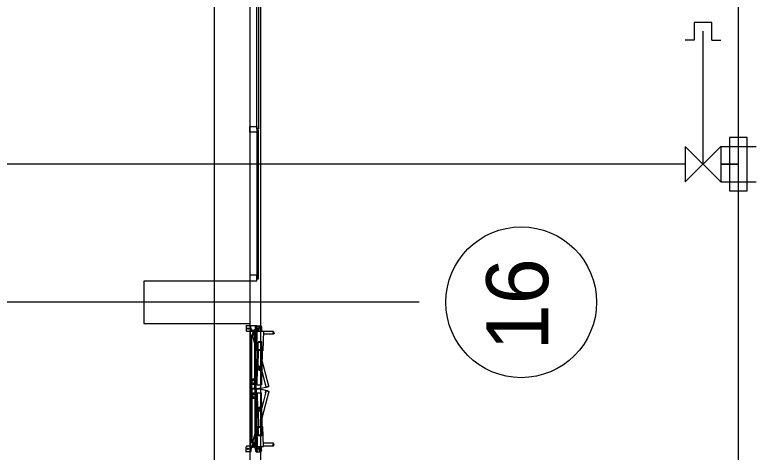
# Model space of a CAD drawing. Extents: x -264205 to -263659, y -1242401 to -1241986.
# Drawn here: x -263798.36 to -263787.89, y -1242184 to -1242177.83 of the extents above; entities that cross this region are included whole.
import ezdxf

# ---------------------------------------------------------------- set-up
doc = ezdxf.new("R2010")
doc.units = 0
for name, color, linetype in [('HESCON_OSI_STAVBY_KFA', 7, 'Continuous'), ('PROJEKT_OBRUBNIKY_KOMUNIKACIE', 7, 'Continuous'), ('SITUACIA_DSP_2D', 7, 'Continuous')]:
    doc.layers.add(name, color=color, linetype=linetype)

msp = doc.modelspace()

# ---------------------------------------------------------------- linework, layer by layer
at = {"layer": 'HESCON_OSI_STAVBY_KFA'}
for p, q in [((-263795.543, -1242083.237), (-263795.543, -1242246.707)), ((-263792.653, -1242181.882), (-263857.913, -1242181.882)), ((-263792.653, -1242181.882), (-263792.653, -1242181.882))]:
    msp.add_line(p, q, dxfattribs=at)
msp.add_circle((-263791.21, -1242181.882), 1.064, dxfattribs=at)
at = {"layer": 'PROJEKT_OBRUBNIKY_KOMUNIKACIE'}
msp.add_lwpolyline([(-263794.893, -1242227.382), (-263808.968, -1242241.457), (-263894.968, -1242241.457), (-263909.043, -1242227.382), (-263909.043, -1242196.333), (-263914.143, -1242196.333), (-263914.143, -1242132.433), (-263909.043, -1242132.433), (-263909.043, -1242101.382), (-263894.968, -1242087.307), (-263808.968, -1242087.307), (-263794.893, -1242101.382), (-263794.893, -1242227.382)], dxfattribs=at)
at = {"layer": 'SITUACIA_DSP_2D'}
for p, q in [((-263788.143, -1242250.14), (-263788.143, -1242082.64)), ((-263794.893, -1242101.382), (-263794.893, -1242227.382)), ((-263795.043, -1242101.769), (-263795.043, -1242226.995)), ((-263794.943, -1242179.432), (-263794.943, -1242177.332)), ((-263794.918, -1242177.332), (-263794.918, -1242179.432)), ((-263788.768, -1242177.932), (-263788.768, -1242178.182)), ((-263788.518, -1242177.932), (-263788.768, -1242177.932)), ((-263788.518, -1242178.182), (-263788.518, -1242177.932)), ((-263788.643, -1242179.932), (-263788.643, -1242178.057)), ((-263788.768, -1242178.182), (-263788.893, -1242178.182)), ((-263788.518, -1242178.182), (-263788.393, -1242178.182)), ((-263795.043, -1242179.482), (-263795.043, -1242179.402)), ((-263795.043, -1242179.402), (-263794.943, -1242179.402)), ((-263794.943, -1242179.402), (-263794.943, -1242179.492)), ((-263794.918, -1242179.432), (-263794.943, -1242179.432)), ((-263794.918, -1242179.452), (-263794.943, -1242179.452)), ((-263794.943, -1242179.452), (-263794.943, -1242181.552)), ((-263794.918, -1242181.552), (-263794.918, -1242179.452)), ((-263794.943, -1242179.482), (-263795.043, -1242179.482)), ((-263794.943, -1242179.492), (-263794.943, -1242179.482)), ((-263788.268, -1242179.557), (-263788.268, -1242180.307)), ((-263788.018, -1242179.557), (-263788.268, -1242179.557)), ((-263788.018, -1242180.307), (-263788.018, -1242179.557)), ((-263788.893, -1242179.682), (-263788.893, -1242180.182)), ((-263788.393, -1242180.182), (-263788.893, -1242179.682)), ((-263788.893, -1242180.182), (-263788.393, -1242179.682)), ((-263788.393, -1242179.682), (-263788.393, -1242180.182)), ((-263788.393, -1242179.682), (-263787.893, -1242179.682)), ((-263788.893, -1242179.932), (-263800.593, -1242179.932)), ((-263788.143, -1242179.932), (-263788.393, -1242179.932)), ((-263788.393, -1242179.932), (-263788.143, -1242179.932)), ((-263788.393, -1242180.182), (-263787.893, -1242180.182)), ((-263788.268, -1242180.307), (-263788.018, -1242180.307)), ((-263794.943, -1242181.497), (-263795.043, -1242181.497)), ((-263795.043, -1242181.497), (-263795.043, -1242181.577)), ((-263794.943, -1242181.537), (-263794.943, -1242181.497)), ((-263794.943, -1242181.577), (-263794.943, -1242181.537)), ((-263795.038, -1242181.582), (-263796.538, -1242181.582)), ((-263796.538, -1242181.582), (-263796.538, -1242182.182)), ((-263795.043, -1242181.577), (-263794.943, -1242181.577)), ((-263795.038, -1242182.182), (-263795.038, -1242181.582)), ((-263794.943, -1242181.552), (-263794.918, -1242181.552)), ((-263796.538, -1242182.182), (-263795.038, -1242182.182)), ((-263795.093, -1242182.208), (-263795.093, -1242182.284)), ((-263795.033, -1242182.214), (-263795.093, -1242182.214)), ((-263795.055, -1242182.254), (-263795.081, -1242182.254)), ((-263795.068, -1242182.241), (-263795.068, -1242182.267)), ((-263795.043, -1242182.208), (-263794.943, -1242182.208)), ((-263795.033, -1242183.102), (-263795.033, -1242182.208)), ((-263795.025, -1242182.224), (-263795.033, -1242182.224)), ((-263795.025, -1242182.245), (-263795.025, -1242182.224)), ((-263794.96, -1242182.245), (-263794.96, -1242182.224)), ((-263794.953, -1242182.224), (-263794.96, -1242182.224)), ((-263794.953, -1242183.102), (-263794.953, -1242182.208)), ((-263794.953, -1242182.213), (-263794.943, -1242182.213)), ((-263794.953, -1242182.213), (-263794.953, -1242182.283)), ((-263794.933, -1242182.223), (-263794.947, -1242182.223)), ((-263794.933, -1242182.272), (-263794.947, -1242182.272)), ((-263794.943, -1242182.213), (-263794.893, -1242182.213)), ((-263794.943, -1242182.213), (-263794.943, -1242182.283)), ((-263794.943, -1242182.232), (-263794.943, -1242182.215)), ((-263794.941, -1242182.215), (-263794.943, -1242182.215)), ((-263794.941, -1242182.232), (-263794.943, -1242182.232)), ((-263794.943, -1242182.253), (-263794.908, -1242182.253)), ((-263794.943, -1242182.281), (-263794.943, -1242182.264)), ((-263794.941, -1242182.264), (-263794.943, -1242182.264)), ((-263794.941, -1242182.232), (-263794.941, -1242182.215)), ((-263794.941, -1242182.23), (-263794.941, -1242182.217)), ((-263794.941, -1242182.217), (-263794.935, -1242182.217)), ((-263794.941, -1242182.223), (-263794.936, -1242182.223)), ((-263794.935, -1242182.23), (-263794.941, -1242182.23)), ((-263794.941, -1242182.281), (-263794.941, -1242182.264)), ((-263794.941, -1242182.279), (-263794.941, -1242182.266)), ((-263794.941, -1242182.266), (-263794.935, -1242182.266)), ((-263794.941, -1242182.272), (-263794.936, -1242182.272)), ((-263794.935, -1242182.217), (-263794.935, -1242182.23)), ((-263794.935, -1242182.266), (-263794.935, -1242182.279)), ((-263794.908, -1242182.254), (-263794.927, -1242182.254)), ((-263794.918, -1242182.253), (-263794.918, -1242182.264)), ((-263794.909, -1242182.289), (-263794.908, -1242182.233)), ((-263794.877, -1242182.233), (-263794.908, -1242182.233)), ((-263794.899, -1242182.223), (-263794.905, -1242182.233)), ((-263794.905, -1242182.233), (-263794.899, -1242182.244)), ((-263794.887, -1242182.223), (-263794.899, -1242182.223)), ((-263794.899, -1242182.244), (-263794.887, -1242182.244)), ((-263794.893, -1242182.218), (-263794.893, -1242182.249)), ((-263794.881, -1242182.233), (-263794.887, -1242182.223)), ((-263794.887, -1242182.244), (-263794.881, -1242182.233)), ((-263794.878, -1242182.234), (-263794.879, -1242182.29)), ((-263795.033, -1242182.294), (-263795.083, -1242182.294)), ((-263794.953, -1242182.288), (-263795.033, -1242182.288)), ((-263794.953, -1242182.294), (-263795.033, -1242182.294)), ((-263795.013, -1242183.097), (-263795.013, -1242182.339)), ((-263794.973, -1242182.339), (-263795.013, -1242182.339)), ((-263795.005, -1242182.288), (-263794.98, -1242182.288)), ((-263795.005, -1242182.288), (-263795.005, -1242182.298)), ((-263795.005, -1242182.298), (-263794.98, -1242182.298)), ((-263795.005, -1242182.339), (-263795.005, -1242182.329)), ((-263795.005, -1242182.329), (-263794.98, -1242182.329)), ((-263795.005, -1242182.343), (-263794.967, -1242182.333)), ((-263795.005, -1242182.339), (-263794.98, -1242182.339)), ((-263794.953, -1242182.54), (-263795.005, -1242182.343)), ((-263794.994, -1242182.298), (-263795.001, -1242182.308)), ((-263795.001, -1242182.319), (-263794.994, -1242182.329)), ((-263794.977, -1242182.325), (-263795.001, -1242182.332)), ((-263794.998, -1242182.341), (-263795.001, -1242182.332)), ((-263794.99, -1242182.329), (-263794.999, -1242182.321)), ((-263794.992, -1242182.298), (-263794.994, -1242182.298)), ((-263794.994, -1242182.329), (-263794.992, -1242182.329)), ((-263794.985, -1242182.308), (-263794.992, -1242182.298)), ((-263794.992, -1242182.329), (-263794.985, -1242182.319)), ((-263794.988, -1242182.328), (-263794.99, -1242182.329)), ((-263794.983, -1242182.317), (-263794.988, -1242182.328)), ((-263794.987, -1242182.305), (-263794.977, -1242182.312)), ((-263794.977, -1242182.314), (-263794.987, -1242182.322)), ((-263794.98, -1242182.288), (-263794.98, -1242182.298)), ((-263794.98, -1242182.339), (-263794.98, -1242182.329)), ((-263794.977, -1242182.301), (-263794.977, -1242182.326)), ((-263794.967, -1242182.301), (-263794.977, -1242182.301)), ((-263794.977, -1242182.312), (-263794.977, -1242182.314)), ((-263794.974, -1242182.335), (-263794.977, -1242182.325)), ((-263794.967, -1242182.326), (-263794.977, -1242182.326)), ((-263794.973, -1242183.097), (-263794.973, -1242182.339)), ((-263794.967, -1242182.333), (-263794.967, -1242182.293)), ((-263794.937, -1242182.293), (-263794.967, -1242182.293)), ((-263794.967, -1242182.301), (-263794.967, -1242182.326)), ((-263794.938, -1242182.333), (-263794.967, -1242182.333)), ((-263794.953, -1242182.386), (-263794.967, -1242182.333)), ((-263794.953, -1242182.283), (-263794.943, -1242182.283)), ((-263794.937, -1242182.294), (-263794.953, -1242182.294)), ((-263794.941, -1242182.281), (-263794.943, -1242182.281)), ((-263794.943, -1242182.564), (-263794.937, -1242182.289)), ((-263794.935, -1242182.279), (-263794.941, -1242182.279)), ((-263794.937, -1242182.289), (-263794.85, -1242182.29)), ((-263794.85, -1242182.29), (-263794.856, -1242182.565)), ((-263794.707, -1242182.333), (-263794.851, -1242182.333)), ((-263794.707, -1242182.293), (-263794.85, -1242182.293)), ((-263794.707, -1242182.305), (-263794.722, -1242182.309)), ((-263794.722, -1242182.309), (-263794.692, -1242182.318)), ((-263794.707, -1242182.293), (-263794.707, -1242182.305)), ((-263794.692, -1242182.318), (-263794.707, -1242182.322)), ((-263794.707, -1242182.322), (-263794.707, -1242182.333)), ((-263794.924, -1242182.564), (-263794.922, -1242182.438)), ((-263794.872, -1242182.439), (-263794.922, -1242182.438)), ((-263794.872, -1242182.449), (-263794.922, -1242182.448)), ((-263794.874, -1242182.565), (-263794.872, -1242182.439)), ((-263794.856, -1242182.565), (-263794.943, -1242182.564)), ((-263794.939, -1242183.045), (-263794.93, -1242182.564)), ((-263794.874, -1242182.555), (-263794.924, -1242182.554)), ((-263794.924, -1242182.787), (-263794.919, -1242182.564)), ((-263794.884, -1242182.788), (-263794.879, -1242182.565)), ((-263794.869, -1242182.565), (-263794.878, -1242183.046)), ((-263794.772, -1242183.066), (-263794.871, -1242182.689)), ((-263794.884, -1242182.788), (-263794.924, -1242182.787)), ((-263794.914, -1242182.792), (-263794.914, -1242182.787)), ((-263794.894, -1242182.792), (-263794.914, -1242182.792)), ((-263794.912, -1242182.792), (-263794.914, -1242182.793)), ((-263794.914, -1242182.799), (-263794.914, -1242182.793)), ((-263794.913, -1242182.8), (-263794.914, -1242182.799)), ((-263794.896, -1242182.8), (-263794.913, -1242182.8)), ((-263794.895, -1242182.792), (-263794.912, -1242182.792)), ((-263794.909, -1242182.799), (-263794.909, -1242182.793)), ((-263794.909, -1242182.808), (-263794.909, -1242182.8)), ((-263794.899, -1242182.8), (-263794.899, -1242182.793)), ((-263794.899, -1242182.808), (-263794.899, -1242182.8)), ((-263794.896, -1242182.8), (-263794.894, -1242182.8)), ((-263794.895, -1242182.792), (-263794.894, -1242182.793)), ((-263794.894, -1242182.792), (-263794.894, -1242182.787)), ((-263794.894, -1242182.8), (-263794.894, -1242182.793)), ((-263794.909, -1242182.808), (-263794.917, -1242182.821)), ((-263794.909, -1242182.808), (-263794.899, -1242182.808)), ((-263794.899, -1242182.808), (-263794.892, -1242182.822)), ((-263794.811, -1242183.076), (-263794.874, -1242182.833)), ((-263795.007, -1242183.04), (-263795.007, -1242182.965)), ((-263794.953, -1242182.965), (-263795.007, -1242182.965)), ((-263795, -1242182.976), (-263794.993, -1242182.972)), ((-263795, -1242182.984), (-263795, -1242182.976)), ((-263794.993, -1242182.988), (-263795, -1242182.984)), ((-263794.993, -1242182.972), (-263794.986, -1242182.976)), ((-263794.986, -1242182.984), (-263794.993, -1242182.988)), ((-263794.986, -1242182.976), (-263794.986, -1242182.984)), ((-263794.947, -1242182.965), (-263794.953, -1242182.965)), ((-263794.947, -1242183.04), (-263794.947, -1242182.965)), ((-263795.033, -1242183.102), (-263795.033, -1242183.997)), ((-263795.015, -1242183.095), (-263795.015, -1242183.065)), ((-263795.013, -1242183.065), (-263795.015, -1242183.065)), ((-263795.015, -1242183.109), (-263795.015, -1242183.139)), ((-263794.973, -1242183.097), (-263795.013, -1242183.097)), ((-263795.013, -1242183.107), (-263795.013, -1242183.866)), ((-263794.973, -1242183.107), (-263795.013, -1242183.107)), ((-263794.975, -1242183.099), (-263795.011, -1242183.099)), ((-263794.975, -1242183.105), (-263795.011, -1242183.105)), ((-263794.953, -1242183.04), (-263795.007, -1242183.04)), ((-263795, -1242183.021), (-263794.993, -1242183.017)), ((-263795, -1242183.029), (-263795, -1242183.021)), ((-263794.993, -1242183.033), (-263795, -1242183.029)), ((-263794.993, -1242183.017), (-263794.986, -1242183.021)), ((-263794.986, -1242183.029), (-263794.993, -1242183.033)), ((-263794.986, -1242183.021), (-263794.986, -1242183.029)), ((-263794.976, -1242183.096), (-263794.967, -1242183.096)), ((-263794.976, -1242183.109), (-263794.967, -1242183.109)), ((-263794.971, -1242183.065), (-263794.973, -1242183.065)), ((-263794.97, -1242183.08), (-263794.973, -1242183.08)), ((-263794.973, -1242183.107), (-263794.973, -1242183.866)), ((-263794.971, -1242183.095), (-263794.971, -1242183.065)), ((-263794.971, -1242183.109), (-263794.971, -1242183.139)), ((-263794.947, -1242183.04), (-263794.953, -1242183.04)), ((-263794.953, -1242183.102), (-263794.953, -1242183.997)), ((-263794.939, -1242183.045), (-263794.878, -1242183.046)), ((-263794.819, -1242183.045), (-263794.821, -1242183.046)), ((-263794.821, -1242183.046), (-263794.814, -1242183.075)), ((-263794.811, -1242183.076), (-263794.772, -1242183.066)), ((-263794.809, -1242183.078), (-263794.774, -1242183.068)), ((-263794.779, -1242183.035), (-263794.781, -1242183.035)), ((-263794.771, -1242183.064), (-263794.779, -1242183.035)), ((-263795.013, -1242183.139), (-263795.015, -1242183.139)), ((-263795.007, -1242183.165), (-263795.007, -1242183.24)), ((-263794.953, -1242183.165), (-263795.007, -1242183.165)), ((-263794.993, -1242183.172), (-263795, -1242183.176)), ((-263795, -1242183.176), (-263795, -1242183.184)), ((-263795, -1242183.184), (-263794.993, -1242183.188)), ((-263794.993, -1242183.217), (-263795, -1242183.221)), ((-263794.986, -1242183.176), (-263794.993, -1242183.172)), ((-263794.993, -1242183.188), (-263794.986, -1242183.184)), ((-263794.986, -1242183.221), (-263794.993, -1242183.217)), ((-263794.986, -1242183.184), (-263794.986, -1242183.176)), ((-263794.97, -1242183.125), (-263794.973, -1242183.125)), ((-263794.971, -1242183.139), (-263794.973, -1242183.139)), ((-263794.947, -1242183.165), (-263794.953, -1242183.165)), ((-263794.947, -1242183.165), (-263794.947, -1242183.24)), ((-263794.939, -1242183.16), (-263794.878, -1242183.159)), ((-263794.939, -1242183.16), (-263794.93, -1242183.641)), ((-263794.869, -1242183.64), (-263794.878, -1242183.159)), ((-263794.811, -1242183.129), (-263794.874, -1242183.372)), ((-263794.772, -1242183.139), (-263794.871, -1242183.516)), ((-263794.821, -1242183.159), (-263794.814, -1242183.13)), ((-263794.819, -1242183.16), (-263794.821, -1242183.159)), ((-263794.811, -1242183.129), (-263794.772, -1242183.139)), ((-263794.809, -1242183.127), (-263794.774, -1242183.137)), ((-263794.779, -1242183.17), (-263794.781, -1242183.17)), ((-263794.771, -1242183.141), (-263794.779, -1242183.17)), ((-263794.953, -1242183.24), (-263795.007, -1242183.24)), ((-263795, -1242183.221), (-263795, -1242183.229)), ((-263795, -1242183.229), (-263794.993, -1242183.233)), ((-263794.993, -1242183.233), (-263794.986, -1242183.229)), ((-263794.986, -1242183.229), (-263794.986, -1242183.221)), ((-263794.947, -1242183.24), (-263794.953, -1242183.24)), ((-263794.884, -1242183.417), (-263794.924, -1242183.418)), ((-263794.924, -1242183.418), (-263794.919, -1242183.641)), ((-263794.909, -1242183.397), (-263794.917, -1242183.384)), ((-263794.913, -1242183.405), (-263794.914, -1242183.406)), ((-263794.914, -1242183.406), (-263794.914, -1242183.412)), ((-263794.912, -1242183.413), (-263794.914, -1242183.412)), ((-263794.914, -1242183.413), (-263794.914, -1242183.418)), ((-263794.894, -1242183.413), (-263794.914, -1242183.413)), ((-263794.896, -1242183.405), (-263794.913, -1242183.405)), ((-263794.895, -1242183.413), (-263794.912, -1242183.413)), ((-263794.909, -1242183.397), (-263794.899, -1242183.397)), ((-263794.909, -1242183.397), (-263794.909, -1242183.405)), ((-263794.909, -1242183.406), (-263794.909, -1242183.412)), ((-263794.899, -1242183.397), (-263794.892, -1242183.383)), ((-263794.899, -1242183.397), (-263794.899, -1242183.405)), ((-263794.899, -1242183.405), (-263794.899, -1242183.412)), ((-263794.896, -1242183.405), (-263794.894, -1242183.405)), ((-263794.895, -1242183.413), (-263794.894, -1242183.412)), ((-263794.894, -1242183.405), (-263794.894, -1242183.412)), ((-263794.894, -1242183.413), (-263794.894, -1242183.418)), ((-263794.884, -1242183.417), (-263794.879, -1242183.64)), ((-263794.953, -1242183.665), (-263795.005, -1242183.862)), ((-263794.856, -1242183.64), (-263794.943, -1242183.641)), ((-263794.943, -1242183.641), (-263794.937, -1242183.916)), ((-263794.924, -1242183.641), (-263794.922, -1242183.767)), ((-263794.874, -1242183.65), (-263794.924, -1242183.651)), ((-263794.874, -1242183.64), (-263794.872, -1242183.766)), ((-263794.85, -1242183.915), (-263794.856, -1242183.64)), ((-263794.953, -1242183.819), (-263794.967, -1242183.872)), ((-263794.872, -1242183.756), (-263794.922, -1242183.757)), ((-263794.872, -1242183.766), (-263794.922, -1242183.767)), ((-263795.093, -1242183.997), (-263795.093, -1242183.921)), ((-263795.033, -1242183.911), (-263795.083, -1242183.911)), ((-263795.055, -1242183.951), (-263795.081, -1242183.951)), ((-263795.068, -1242183.964), (-263795.068, -1242183.938)), ((-263794.953, -1242183.911), (-263795.033, -1242183.911)), ((-263794.953, -1242183.917), (-263795.033, -1242183.917)), ((-263794.973, -1242183.866), (-263795.013, -1242183.866)), ((-263795.005, -1242183.862), (-263794.967, -1242183.872)), ((-263795.005, -1242183.866), (-263795.005, -1242183.876)), ((-263795.005, -1242183.866), (-263794.98, -1242183.866)), ((-263795.005, -1242183.876), (-263794.98, -1242183.876)), ((-263795.005, -1242183.907), (-263794.98, -1242183.907)), ((-263795.005, -1242183.917), (-263795.005, -1242183.907)), ((-263795.005, -1242183.917), (-263794.98, -1242183.917)), ((-263794.998, -1242183.864), (-263795.001, -1242183.873)), ((-263794.977, -1242183.88), (-263795.001, -1242183.873)), ((-263795.001, -1242183.886), (-263794.994, -1242183.876)), ((-263794.994, -1242183.907), (-263795.001, -1242183.897)), ((-263794.99, -1242183.876), (-263794.999, -1242183.884)), ((-263794.994, -1242183.876), (-263794.992, -1242183.876)), ((-263794.992, -1242183.907), (-263794.994, -1242183.907)), ((-263794.992, -1242183.876), (-263794.985, -1242183.886)), ((-263794.985, -1242183.897), (-263794.992, -1242183.907)), ((-263794.988, -1242183.877), (-263794.99, -1242183.876)), ((-263794.983, -1242183.888), (-263794.988, -1242183.877)), ((-263794.977, -1242183.89), (-263794.987, -1242183.883)), ((-263794.987, -1242183.9), (-263794.977, -1242183.892)), ((-263794.98, -1242183.866), (-263794.98, -1242183.876)), ((-263794.98, -1242183.917), (-263794.98, -1242183.907)), ((-263794.974, -1242183.87), (-263794.977, -1242183.88)), ((-263794.977, -1242183.904), (-263794.977, -1242183.879)), ((-263794.967, -1242183.879), (-263794.977, -1242183.879)), ((-263794.977, -1242183.892), (-263794.977, -1242183.89)), ((-263794.967, -1242183.904), (-263794.977, -1242183.904)), ((-263794.967, -1242183.871), (-263794.967, -1242183.911)), ((-263794.938, -1242183.871), (-263794.967, -1242183.871)), ((-263794.967, -1242183.904), (-263794.967, -1242183.879)), ((-263794.937, -1242183.911), (-263794.967, -1242183.911)), ((-263794.937, -1242183.911), (-263794.953, -1242183.911)), ((-263794.953, -1242183.922), (-263794.943, -1242183.922)), ((-263794.953, -1242183.992), (-263794.953, -1242183.922)), ((-263794.933, -1242183.932), (-263794.947, -1242183.932)), ((-263794.943, -1242183.992), (-263794.943, -1242183.922)), ((-263794.943, -1242183.924), (-263794.943, -1242183.941)), ((-263794.941, -1242183.924), (-263794.943, -1242183.924)), ((-263794.941, -1242183.941), (-263794.943, -1242183.941)), ((-263794.943, -1242183.951), (-263794.908, -1242183.951)), ((-263794.941, -1242183.924), (-263794.941, -1242183.941)), ((-263794.941, -1242183.926), (-263794.941, -1242183.939)), ((-263794.935, -1242183.926), (-263794.941, -1242183.926)), ((-263794.941, -1242183.932), (-263794.936, -1242183.932)), ((-263794.941, -1242183.939), (-263794.935, -1242183.939)), ((-263794.937, -1242183.916), (-263794.85, -1242183.915)), ((-263794.935, -1242183.939), (-263794.935, -1242183.926)), ((-263794.908, -1242183.951), (-263794.927, -1242183.951)), ((-263794.918, -1242183.951), (-263794.918, -1242183.941)), ((-263794.909, -1242183.916), (-263794.908, -1242183.972)), ((-263794.878, -1242183.971), (-263794.879, -1242183.915)), ((-263794.707, -1242183.871), (-263794.851, -1242183.871)), ((-263794.707, -1242183.911), (-263794.85, -1242183.911)), ((-263794.722, -1242183.896), (-263794.692, -1242183.887)), ((-263794.707, -1242183.9), (-263794.722, -1242183.896)), ((-263794.707, -1242183.883), (-263794.707, -1242183.871)), ((-263794.692, -1242183.887), (-263794.707, -1242183.883)), ((-263794.707, -1242183.911), (-263794.707, -1242183.9)), ((-263795.033, -1242183.991), (-263795.093, -1242183.991)), ((-263795.025, -1242183.981), (-263795.033, -1242183.981)), ((-263795.025, -1242183.96), (-263795.025, -1242183.981)), ((-263794.96, -1242183.96), (-263794.96, -1242183.981)), ((-263794.953, -1242183.981), (-263794.96, -1242183.981)), ((-263794.953, -1242183.992), (-263794.943, -1242183.992)), ((-263794.933, -1242183.981), (-263794.947, -1242183.981)), ((-263794.943, -1242183.973), (-263794.943, -1242183.99)), ((-263794.941, -1242183.973), (-263794.943, -1242183.973)), ((-263794.941, -1242183.99), (-263794.943, -1242183.99)), ((-263794.943, -1242183.991), (-263794.893, -1242183.991)), ((-263794.941, -1242183.973), (-263794.941, -1242183.99)), ((-263794.941, -1242183.975), (-263794.941, -1242183.988)), ((-263794.935, -1242183.975), (-263794.941, -1242183.975)), ((-263794.941, -1242183.981), (-263794.936, -1242183.981)), ((-263794.941, -1242183.988), (-263794.935, -1242183.988)), ((-263794.935, -1242183.988), (-263794.935, -1242183.975)), ((-263794.877, -1242183.971), (-263794.908, -1242183.971)), ((-263794.905, -1242183.971), (-263794.899, -1242183.961)), ((-263794.899, -1242183.982), (-263794.905, -1242183.971)), ((-263794.899, -1242183.961), (-263794.887, -1242183.961)), ((-263794.887, -1242183.982), (-263794.899, -1242183.982)), ((-263794.893, -1242183.987), (-263794.893, -1242183.956)), ((-263794.887, -1242183.961), (-263794.881, -1242183.971)), ((-263794.881, -1242183.971), (-263794.887, -1242183.982))]:
    msp.add_line(p, q, dxfattribs=at)
for centre, radius in [((-263795.068, -1242182.254), 0.008), ((-263794.893, -1242182.233), 0.0126), ((-263794.893, -1242182.233), 0.0102), ((-263794.905, -1242182.828), 0.00952), ((-263794.905, -1242182.828), 0.00645), ((-263794.905, -1242182.828), 0.005), ((-263794.993, -1242182.98), 0.0084), ((-263794.993, -1242182.98), 0.0068), ((-263794.993, -1242183.025), 0.0084), ((-263794.993, -1242183.025), 0.0068), ((-263794.993, -1242183.18), 0.0084), ((-263794.993, -1242183.225), 0.0084), ((-263794.993, -1242183.18), 0.0068), ((-263794.993, -1242183.225), 0.0068), ((-263794.905, -1242183.377), 0.00952), ((-263794.905, -1242183.377), 0.00645), ((-263794.905, -1242183.377), 0.005), ((-263795.068, -1242183.951), 0.008), ((-263794.893, -1242183.971), 0.0126), ((-263794.893, -1242183.971), 0.0102)]:
    msp.add_circle(centre, radius, dxfattribs=at)
for centre, radius, start, end in [((-263794.993, -1242182.245), 0.0325, 180, 0), ((-263794.942, -1242182.22), 0.0068, 330, 30), ((-263794.942, -1242182.227), 0.0068, 330, 30), ((-263794.942, -1242182.269), 0.0068, 330, 30), ((-263794.942, -1242182.276), 0.0068, 330, 30), ((-263794.918, -1242182.254), 0.008, 176.4167, 3.5833), ((-263794.893, -1242182.233), 0.015, 358.86, 178.86), ((-263794.893, -1242182.233), 0.02, 317.4504, 90), ((-263795.083, -1242182.284), 0.01, 180, 270), ((-263794.993, -1242182.313), 0.01, 323.6139, 216.3861), ((-263794.993, -1242182.313), 0.01, 53.6139, 306.3861), ((-263794.993, -1242182.313), 0.01, 338.6139, 231.3861), ((-263794.993, -1242182.313), 0.01, 143.6139, 36.3861), ((-263794.911, -1242182.796), 0.00432, 54.2666, 123.4534), ((-263794.911, -1242182.796), 0.00432, 234.2666, 303.4534), ((-263794.904, -1242182.808), 0.0161, 71.1601, 106.5599), ((-263794.904, -1242182.784), 0.0161, 251.1601, 286.5599), ((-263794.897, -1242182.797), 0.00432, 54.2666, 123.4534), ((-263794.899, -1242182.793), 0.0001, 178.86, 248.0468), ((-263794.899, -1242182.8), 0.0001, 109.6732, 178.86), ((-263794.897, -1242182.796), 0.00432, 234.2666, 303.4534), ((-263794.905, -1242182.828), 0.014, 150.1229, 27.5971), ((-263795.011, -1242183.095), 0.004, 180, 270), ((-263795.011, -1242183.109), 0.004, 90, 180), ((-263794.993, -1242182.313), 0.786, 270, 285), ((-263794.993, -1242183.891), 0.786, 75, 90), ((-263794.975, -1242183.095), 0.004, 270, 0), ((-263794.975, -1242183.109), 0.004, 0, 90), ((-263794.81, -1242183.074), 0.004, 195, 285), ((-263794.775, -1242183.065), 0.004, 285, 15), ((-263794.81, -1242183.131), 0.004, 75, 165), ((-263794.775, -1242183.14), 0.004, 345, 75), ((-263794.905, -1242183.377), 0.014, 332.4029, 209.8771), ((-263794.911, -1242183.409), 0.00432, 56.5466, 125.7334), ((-263794.911, -1242183.409), 0.00432, 236.5466, 305.7334), ((-263794.904, -1242183.421), 0.0161, 73.4401, 108.8399), ((-263794.904, -1242183.397), 0.0161, 253.4401, 288.8399), ((-263794.897, -1242183.409), 0.00432, 56.5466, 125.7334), ((-263794.899, -1242183.405), 0.0001, 181.14, 250.3268), ((-263794.897, -1242183.408), 0.00432, 236.5466, 305.7334), ((-263794.899, -1242183.412), 0.0001, 111.9532, 181.14), ((-263795.083, -1242183.921), 0.01, 90, 180), ((-263794.993, -1242183.96), 0.0325, 0, 180), ((-263794.993, -1242183.891), 0.01, 323.6139, 216.3861), ((-263794.993, -1242183.891), 0.01, 53.6139, 306.3861), ((-263794.993, -1242183.891), 0.01, 128.6139, 21.3861), ((-263794.993, -1242183.891), 0.01, 143.6139, 36.3861), ((-263794.942, -1242183.929), 0.0068, 330, 30), ((-263794.942, -1242183.936), 0.0068, 330, 30), ((-263794.918, -1242183.951), 0.008, 356.4167, 183.5833), ((-263794.942, -1242183.978), 0.0068, 330, 30), ((-263794.942, -1242183.985), 0.0068, 330, 30), ((-263794.893, -1242183.971), 0.015, 181.14, 1.14), ((-263794.893, -1242183.971), 0.02, 270, 42.5496)]:
    msp.add_arc(centre, radius, start, end, dxfattribs=at)

# ---------------------------------------------------------------- texts
at = {"layer": 'HESCON_OSI_STAVBY_KFA'}
msp.add_text('16', height=0.875, rotation=90, dxfattribs=at).set_placement((-263790.829, -1242182.562))

doc.saveas('drawing.dxf')
